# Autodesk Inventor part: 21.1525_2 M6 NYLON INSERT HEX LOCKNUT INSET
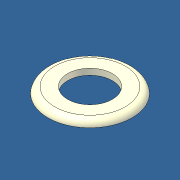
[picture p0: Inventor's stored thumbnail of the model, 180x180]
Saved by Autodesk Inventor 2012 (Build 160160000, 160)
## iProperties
Created: 2012-02
Part Number: 21.1525_2 M6 NYLON INSERT HEX LOCKNUT INSET
Material: Nylon-6/6
Document SubType Name: Modeling
Designer: Administrator
Mass: 0.0361221 g
Surface Area: 1.24192 cm^2
Volume: 0.0319664 cm^3
Density: 1.13 g/cm^3
Author: Administrator
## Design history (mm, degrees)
feature "Base1"
body "Solid1"
